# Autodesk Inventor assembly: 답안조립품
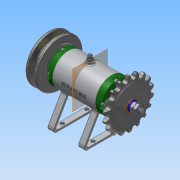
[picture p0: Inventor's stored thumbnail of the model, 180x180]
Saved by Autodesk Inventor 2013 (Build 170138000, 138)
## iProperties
Created: 2016-03
Part Number: 답안조립품
Document SubType Name: Assembly
Designer: Administrator
Author: Administrator
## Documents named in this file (16)
- C:\Users\Administrator\Desktop\460307V1014\답안조립품.iam
- C:\Users\Administrator\Desktop\460307V1014\1-본체.ipt
- C:\Users\Administrator\Desktop\460307V1014\베어링 15 x 32 x 9.ipt
- C:\Users\Administrator\Desktop\460307V1014\커버.ipt
- C:\Users\Administrator\Desktop\460307V1014\오일 실 15 25 7.ipt
- C:\Users\Administrator\Desktop\460307V1014\축.ipt
- C:\Users\Administrator\Desktop\460307V1014\볼트 M4 x 12.ipt
- C:\Users\Administrator\Desktop\460307V1014\키 3 x 3 x 12.ipt
- C:\Users\Administrator\Desktop\460307V1014\스프로킷.ipt
- C:\Users\Administrator\Desktop\460307V1014\V벨트풀리.ipt
- C:\Users\Administrator\Desktop\460307V1014\와셔 8x17.ipt
- C:\Users\Administrator\Desktop\460307V1014\스프링와셔 8.ipt
- C:\Users\Administrator\Desktop\460307V1014\너트 M 8.ipt
- C:\Users\Administrator\Desktop\460307V1014\와셔 6x11.5.ipt
- C:\Users\Administrator\Desktop\460307V1014\볼트 M 6 x 8.ipt
- C:\Users\Administrator\Desktop\460307V1014\니플 M 6 x 0.75.ipt
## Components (12 placed, 4 different names)
1. 1-본체:1
2. KS B 2023 6002 - 15 x 32 x 9:1
3. KS B 2023 6002 - 15 x 32 x 9:2
4. V벨트풀리:1 — 각도:2
5. ISO 4762 M4 x 12:2
6. ISO 4762 M4 x 12:3
7. ISO 4762 M4 x 12:4
8. ISO 4762 M4 x 12:5
9. ISO 4762 M4 x 12:1
10. ISO 4762 M4 x 12:6
11. ISO 4762 M4 x 12:7
12. ISO 4762 M4 x 12:8
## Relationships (1: Angle 1)
- 각도:2 [Angle]: V벨트풀리:1
